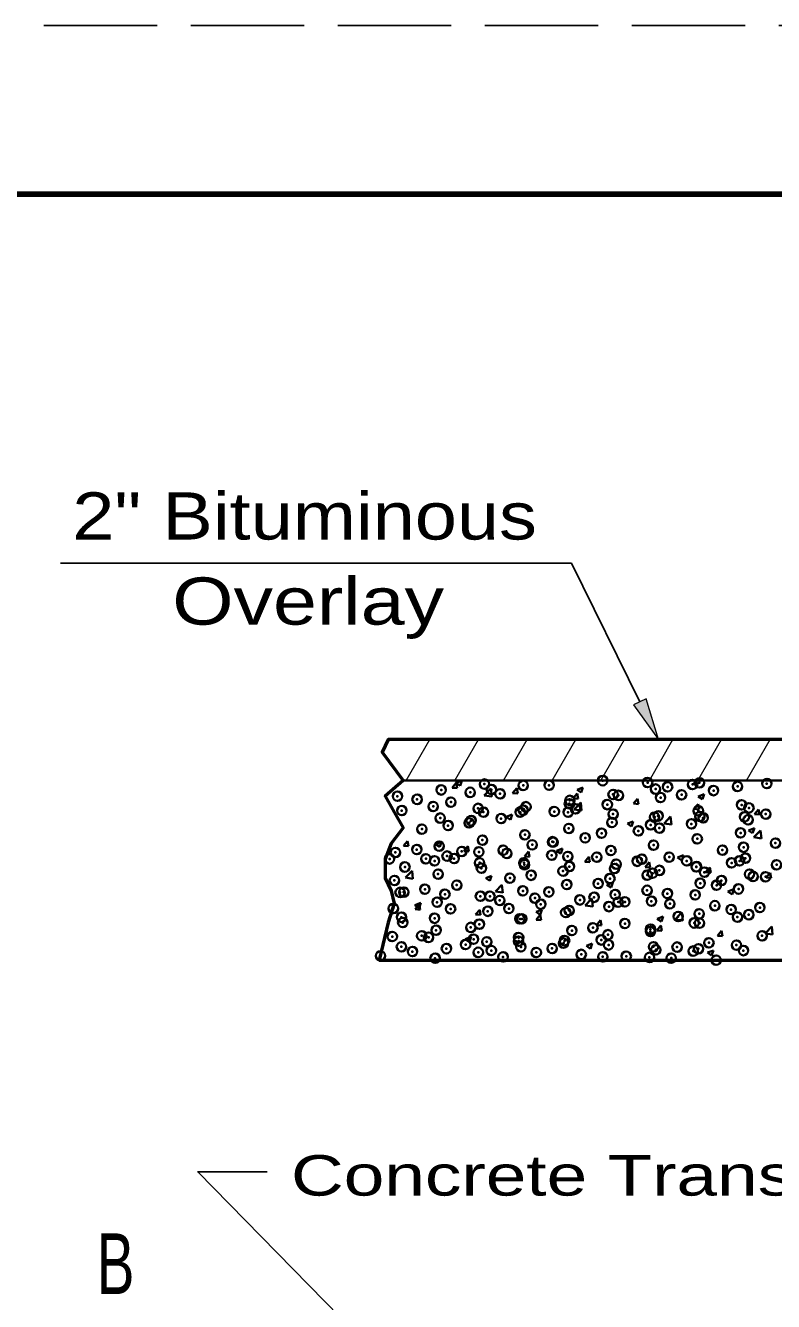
# Model space of a CAD drawing. Extents: x 14 to 49.3, y 28 to 50.
# Drawn here: x 17.83 to 20.049, y 46.258 to 50.044 of the extents above; entities that cross this region are included whole.
import ezdxf

# ---------------------------------------------------------------- set-up
doc = ezdxf.new("R2010")
doc.units = 0
doc.header["$LTSCALE"] = 0.056
doc.header["$PDMODE"] = 32
doc.header["$PDSIZE"] = 0.028
doc.linetypes.add('LONG_DASHED', pattern=[7.5, 6, -1.5])
for name, color, linetype, lineweight in [('1', 7, 'Continuous', 35), ('3', 7, 'Continuous', 13), ('5', 7, 'Continuous', 35)]:
    doc.layers.add(name, color=color, linetype=linetype, lineweight=lineweight)

msp = doc.modelspace()

# ---------------------------------------------------------------- hatches: boundary and pattern name
at = {"layer": '3'}
msp.add_hatch(color=256, dxfattribs=at).paths.add_polyline_path([(19.671, 48.04683), (19.63367, 48.02842), (19.70767, 47.92558), (19.70767, 47.92558)])

# ---------------------------------------------------------------- linework, layer by layer
at = {"layer": '1', "linetype": 'LONG_DASHED', "lineweight": 25}
msp.add_line((49.17658, 50.04392), (13.97658, 50.04392), dxfattribs=at)
at = {"layer": '1', "lineweight": 158}
msp.add_line((49.09325, 49.54392), (16.59325, 49.54392), dxfattribs=at)
at = {"layer": '1', "lineweight": 13}
for p, q in [((18.95892, 47.804), (19.02917, 47.92558)), ((19.10325, 47.804), (19.1735, 47.92558)), ((19.24767, 47.804), (19.31783, 47.92558)), ((19.392, 47.804), (19.46217, 47.92558)), ((19.53633, 47.804), (19.6065, 47.92558)), ((19.68067, 47.804), (19.75083, 47.92558)), ((19.825, 47.804), (19.89517, 47.92558)), ((19.96933, 47.804), (20.0395, 47.92558))]:
    msp.add_line(p, q, dxfattribs=at)
at = {"layer": '1'}
for p, q in [((18.94333, 47.798), (18.94608, 47.79758)), ((18.94608, 47.79758), (18.94575, 47.80017)), ((20.38492, 47.804), (18.95017, 47.804)), ((19.09583, 47.7825), (19.10783, 47.79692)), ((19.09583, 47.7825), (19.11075, 47.78125)), ((19.10692, 47.79667), (19.12442, 47.80342)), ((19.10692, 47.79667), (19.11942, 47.78833)), ((19.11075, 47.78117), (19.10783, 47.79692)), ((19.11942, 47.78833), (19.1245, 47.80342)), ((19.19067, 47.75967), (19.21017, 47.77992)), ((19.21292, 47.75617), (19.21017, 47.77992)), ((19.27508, 47.76683), (19.28717, 47.78117)), ((19.29008, 47.7655), (19.28717, 47.78117)), ((19.46625, 47.77667), (19.48375, 47.78342)), ((19.46625, 47.77667), (19.47867, 47.76825)), ((19.47867, 47.76825), (19.48375, 47.78342)), ((19.19067, 47.75967), (19.21292, 47.75617)), ((19.27508, 47.76683), (19.29008, 47.7655)), ((19.45442, 47.75117), (19.4665, 47.7655)), ((19.45442, 47.75117), (19.46933, 47.74983)), ((19.4575, 47.71825), (19.47692, 47.73858)), ((19.46942, 47.74983), (19.4665, 47.7655)), ((19.47975, 47.71483), (19.47692, 47.73858)), ((19.63375, 47.73542), (19.64583, 47.74983)), ((19.63375, 47.73542), (19.64867, 47.73417)), ((19.64867, 47.73417), (19.64583, 47.74983)), ((19.8255, 47.75667), (19.843, 47.76333)), ((19.8255, 47.75667), (19.83792, 47.74825)), ((19.838, 47.74825), (19.843, 47.76333)), ((19.25617, 47.696), (19.27367, 47.70275)), ((19.26858, 47.68767), (19.27367, 47.70275)), ((19.4575, 47.71825), (19.47967, 47.71483)), ((19.81308, 47.71975), (19.82508, 47.73417)), ((19.81308, 47.71975), (19.828, 47.7185)), ((19.828, 47.71842), (19.82508, 47.73417)), ((19.99233, 47.70408), (20.00442, 47.71842)), ((19.99233, 47.70408), (20.00733, 47.70275)), ((20.00733, 47.70275), (20.00442, 47.71842)), ((19.25617, 47.696), (19.26858, 47.68767)), ((19.61542, 47.676), (19.633, 47.68275)), ((19.61542, 47.676), (19.62792, 47.66758)), ((19.62792, 47.66758), (19.633, 47.68275)), ((19.72425, 47.67692), (19.74375, 47.69717)), ((19.72425, 47.67692), (19.74375, 47.69717)), ((19.72425, 47.67692), (19.7465, 47.67342)), ((19.7465, 47.67342), (19.74375, 47.69717)), ((19.97475, 47.656), (19.99225, 47.66267)), ((19.98717, 47.64758), (19.99225, 47.66267)), ((18.95117, 47.61017), (18.96325, 47.6245)), ((18.96617, 47.60883), (18.96325, 47.6245)), ((19.04608, 47.61542), (19.06358, 47.62208)), ((19.05858, 47.607), (19.06367, 47.62208)), ((19.97475, 47.656), (19.98717, 47.64758)), ((19.99108, 47.6355), (20.01058, 47.65583)), ((19.99108, 47.6355), (20.01333, 47.63208)), ((20.01333, 47.63208), (20.01058, 47.65583)), ((18.95117, 47.61017), (18.96608, 47.60883)), ((19.04608, 47.61542), (19.05858, 47.607)), ((19.1305, 47.5945), (19.1425, 47.60883)), ((19.1305, 47.5945), (19.14542, 47.59317)), ((19.14542, 47.59317), (19.14258, 47.60883)), ((19.30983, 47.57875), (19.32183, 47.59317)), ((19.32475, 47.5775), (19.32183, 47.59317)), ((19.40542, 47.59542), (19.42292, 47.60208)), ((19.40542, 47.59542), (19.41783, 47.587)), ((19.41783, 47.587), (19.42292, 47.60208)), ((19.30983, 47.57875), (19.32475, 47.5775)), ((19.48908, 47.56308), (19.50117, 47.5775)), ((19.48908, 47.56308), (19.50408, 47.56175)), ((19.50408, 47.56175), (19.50117, 47.57742)), ((19.66842, 47.54742), (19.6805, 47.56175)), ((19.66842, 47.54742), (19.68333, 47.54608)), ((19.68342, 47.54608), (19.6805, 47.56175)), ((19.76467, 47.57533), (19.78217, 47.58208)), ((19.76467, 47.57533), (19.77708, 47.567)), ((19.77717, 47.567), (19.78217, 47.58208)), ((19.84775, 47.53175), (19.85983, 47.54608)), ((19.86267, 47.53042), (19.85983, 47.54608)), ((18.957, 47.51608), (18.9765, 47.53642)), ((18.957, 47.51608), (18.97925, 47.51267)), ((18.97925, 47.51267), (18.9765, 47.53642)), ((19.19533, 47.51475), (19.21283, 47.5215)), ((19.19533, 47.51475), (19.20775, 47.50633)), ((19.20783, 47.50633), (19.21283, 47.5215)), ((19.84775, 47.53175), (19.86267, 47.53042)), ((20.02708, 47.516), (20.03908, 47.53042)), ((20.02708, 47.516), (20.042, 47.51475)), ((20.042, 47.51475), (20.03908, 47.53042)), ((19.22383, 47.47475), (19.24325, 47.495)), ((19.22383, 47.47475), (19.246, 47.47133)), ((19.24608, 47.47125), (19.24325, 47.495)), ((19.55467, 47.49475), (19.57217, 47.50142)), ((19.55467, 47.49475), (19.56708, 47.48633)), ((19.56708, 47.48633), (19.57217, 47.50142)), ((19.91392, 47.47467), (19.93142, 47.48142)), ((19.91392, 47.47467), (19.92633, 47.46633)), ((19.92633, 47.46633), (19.93142, 47.48142)), ((18.98525, 47.43408), (19.00283, 47.44083)), ((18.98525, 47.43408), (18.99775, 47.42575)), ((18.98583, 47.42208), (18.99792, 47.4365)), ((18.99775, 47.42575), (19.00283, 47.44083)), ((19.00083, 47.42083), (18.99792, 47.4365)), ((19.49058, 47.43333), (19.51008, 47.45367)), ((19.49058, 47.43333), (19.51283, 47.42992)), ((19.51283, 47.42992), (19.51008, 47.45367)), ((18.98583, 47.42208), (19.00083, 47.42083)), ((19.16517, 47.40642), (19.17725, 47.42075)), ((19.16517, 47.40642), (19.18008, 47.40508)), ((19.18017, 47.40508), (19.17725, 47.42075)), ((19.3445, 47.39075), (19.3565, 47.40508)), ((19.34458, 47.41408), (19.36208, 47.42083)), ((19.34458, 47.41408), (19.357, 47.40567)), ((19.35942, 47.38942), (19.35658, 47.40508)), ((19.357, 47.40567), (19.36208, 47.42083)), ((19.70383, 47.39408), (19.72133, 47.40075)), ((19.71633, 47.38567), (19.72133, 47.40075)), ((19.75742, 47.392), (19.77692, 47.41225)), ((19.77967, 47.3885), (19.77692, 47.41225)), ((19.3445, 47.39075), (19.35942, 47.38942)), ((19.52383, 47.37508), (19.53583, 47.38942)), ((19.52383, 47.37508), (19.53875, 47.37375)), ((19.53875, 47.37375), (19.53583, 47.38942)), ((19.70308, 47.35933), (19.71517, 47.37375)), ((19.70308, 47.35933), (19.71808, 47.35808)), ((19.70383, 47.39408), (19.71625, 47.38567)), ((19.71808, 47.35808), (19.71517, 47.37375)), ((19.75742, 47.392), (19.77967, 47.3885)), ((19.88242, 47.34367), (19.8945, 47.358)), ((19.89742, 47.34233), (19.8945, 47.358)), ((20.02425, 47.35058), (20.04367, 47.37092)), ((20.0465, 47.34717), (20.04375, 47.37092)), ((19.1345, 47.33342), (19.152, 47.34017)), ((19.1345, 47.33342), (19.14692, 47.32508)), ((19.147, 47.32508), (19.152, 47.34017)), ((19.49383, 47.31342), (19.51133, 47.32017)), ((19.50625, 47.30508), (19.51133, 47.32017)), ((19.88242, 47.34367), (19.89733, 47.34233)), ((20.02425, 47.35058), (20.0465, 47.34717)), ((19.49383, 47.31342), (19.50625, 47.30508)), ((19.85308, 47.29342), (19.87058, 47.30017)), ((19.85308, 47.29342), (19.8655, 47.285)), ((19.8655, 47.285), (19.87058, 47.30017))]:
    msp.add_line(p, q, dxfattribs=at)
at = {"layer": '1', "lineweight": 53}
for points in [[(20.38492, 47.92558), (18.90558, 47.92558), (18.88775, 47.88817), (18.95017, 47.804)], [(18.95017, 47.804), (18.89667, 47.75725), (18.92342, 47.7105), (18.95017, 47.66375), (18.9145, 47.617), (18.89667, 47.57025), (18.89667, 47.51417), (18.9145, 47.47675), (18.92342, 47.43933), (18.90558, 47.38325), (18.87883, 47.271)], [(18.87883, 47.271), (23.89617, 47.271), (23.90508, 47.29908), (23.88725, 47.34583), (23.86942, 47.39258), (23.89617, 47.43933), (23.92292, 47.47675), (23.914, 47.51417), (23.87833, 47.57958), (23.8605, 47.63567), (23.89617, 47.66375), (23.914, 47.77592), (23.914, 47.79467)]]:
    msp.add_lwpolyline(points, dxfattribs=at)
at = {"layer": '1'}
for p in [(19.54217, 47.80358), (19.67558, 47.79792), (19.829, 47.79742), (19.06308, 47.776), (19.14933, 47.76892), (19.1915, 47.79358), (19.21192, 47.77717), (19.23758, 47.76483), (19.30658, 47.78967), (19.38342, 47.78992), (19.57292, 47.76267), (19.58908, 47.76), (19.69917, 47.77875), (19.73492, 47.785), (19.7765, 47.76158), (19.80908, 47.79225), (19.87117, 47.774), (19.9425, 47.78667), (20.029, 47.79483), (18.93325, 47.75725), (18.99142, 47.74817), (19.03933, 47.727), (19.09183, 47.73983), (19.17275, 47.72133), (19.31467, 47.72633), (19.44333, 47.735), (19.44458, 47.74508), (19.556, 47.7325), (19.71392, 47.75333), (19.95433, 47.73183), (19.97617, 47.72258), (18.946, 47.71483), (19.06008, 47.69275), (19.15175, 47.68492), (19.18842, 47.71033), (19.24083, 47.691), (19.2975, 47.71), (19.30625, 47.71567), (19.39875, 47.71183), (19.43967, 47.71008), (19.46133, 47.72008), (19.57317, 47.70442), (19.69617, 47.6955), (19.70658, 47.69875), (19.826, 47.71425), (19.83042, 47.69758), (19.84008, 47.69317), (19.96325, 47.69617), (19.9735, 47.6875), (20.02583, 47.70442), (19.00592, 47.65992), (19.08358, 47.67033), (19.14617, 47.67858), (19.4415, 47.66192), (19.53883, 47.6475), (19.56983, 47.6795), (19.64808, 47.65467), (19.68458, 47.6725), (19.71067, 47.66292), (19.80542, 47.67542), (19.95133, 47.64858), (19.057, 47.6095), (19.18542, 47.62717), (19.31167, 47.64317), (19.333, 47.61325), (19.393, 47.6225), (19.39558, 47.62142), (19.49025, 47.63392), (19.69308, 47.61225), (19.82292, 47.631), (20.05475, 47.61833), (18.90992, 47.57125), (18.92717, 47.59075), (18.99067, 47.59925), (19.01783, 47.57175), (19.08042, 47.58), (19.10142, 47.57242), (19.12408, 47.59358), (19.17508, 47.59242), (19.24717, 47.59742), (19.25758, 47.58792), (19.391, 47.58233), (19.4385, 47.57867), (19.5245, 47.57667), (19.56683, 47.59625), (19.65792, 47.571), (19.73958, 47.57683), (19.8975, 47.59758), (19.96008, 47.60583), (19.96583, 47.57342), (18.95558, 47.54742), (19.04333, 47.56567), (19.17683, 47.56), (19.18233, 47.54392), (19.30867, 47.55992), (19.31025, 47.55433), (19.4245, 47.53533), (19.44375, 47.54875), (19.57717, 47.54308), (19.58233, 47.55608), (19.64492, 47.56433), (19.71067, 47.53742), (19.79142, 47.56542), (19.81992, 47.54775), (19.82008, 47.54842), (19.92483, 47.55975), (19.94825, 47.56542), (20.05825, 47.55408), (18.92417, 47.50758), (19.054, 47.52633), (19.26717, 47.51458), (19.32975, 47.52283), (19.43542, 47.49542), (19.5285, 47.49833), (19.56383, 47.513), (19.67425, 47.52333), (19.69008, 47.529), (19.83175, 47.499), (19.84408, 47.53183), (19.89433, 47.50725), (19.97758, 47.52617), (19.989, 47.51967), (20.02575, 47.5185), (18.94092, 47.47217), (18.952, 47.47308), (19.01458, 47.48133), (19.07433, 47.4665), (19.10933, 47.49383), (19.17933, 47.46067), (19.20783, 47.46083), (19.30558, 47.47667), (19.38267, 47.47333), (19.51658, 47.4575), (19.57917, 47.46575), (19.67383, 47.47817), (19.73417, 47.4685), (19.81692, 47.46458), (19.88, 47.4935), (19.94525, 47.48217), (18.92108, 47.42433), (19.05092, 47.44308), (19.09108, 47.42325), (19.23692, 47.44825), (19.264, 47.42425), (19.34125, 47.45525), (19.35867, 47.43675), (19.44258, 47.41842), (19.47475, 47.44958), (19.56075, 47.42983), (19.58833, 47.44342), (19.60817, 47.44392), (19.687, 47.44583), (19.74167, 47.43833), (19.87508, 47.43267), (19.92325, 47.42108), (20.00858, 47.427), (18.94525, 47.39825), (18.94883, 47.38275), (19.0435, 47.39525), (19.20142, 47.416), (19.29675, 47.39342), (19.30258, 47.3935), (19.43242, 47.41217), (19.766, 47.40042), (19.81383, 47.38133), (19.82858, 47.40867), (19.82967, 47.381), (19.94217, 47.39892), (19.97542, 47.406), (19.00517, 47.34333), (19.04792, 47.35983), (19.151, 47.36833), (19.17625, 47.3775), (19.45083, 47.35892), (19.51342, 47.36717), (19.55775, 47.34658), (19.60808, 47.37958), (19.68383, 47.35592), (19.684, 47.36258), (20.01533, 47.34325), (18.91808, 47.34108), (18.94492, 47.31083), (19.02567, 47.33875), (19.07842, 47.30517), (19.13567, 47.31742), (19.15917, 47.33308), (19.19825, 47.32567), (19.29258, 47.3275), (19.29292, 47.33808), (19.2995, 47.31025), (19.39225, 47.30592), (19.42608, 47.32183), (19.42933, 47.329), (19.53808, 47.33092), (19.5595, 47.31617), (19.69292, 47.31058), (19.76275, 47.31), (19.82642, 47.30492), (19.8575, 47.3225), (19.93917, 47.31575), (18.88308, 47.28417), (18.97775, 47.29658), (19.04483, 47.27667), (19.17325, 47.29425), (19.21183, 47.2995), (19.2465, 47.28083), (19.34533, 47.29392), (19.47875, 47.28825), (19.54233, 47.281), (19.61225, 47.28258), (19.68092, 47.27933), (19.70017, 47.30175), (19.74567, 47.277), (19.81083, 47.29808), (19.87908, 47.27133), (19.95983, 47.29925)]:
    msp.add_point(p, dxfattribs=at)
at = {"layer": '3', "lineweight": 25}
for points in [[(19.65233, 48.03767), (19.44925, 48.44917), (17.93383, 48.44917)], [(19.09325, 45.87442), (18.34083, 46.643), (18.54708, 46.643)]]:
    msp.add_lwpolyline(points, dxfattribs=at)
at = {"layer": '3'}
msp.add_lwpolyline([(19.671, 48.04683), (19.63367, 48.02842), (19.70767, 47.92558), (19.70767, 47.92558)], close=True, dxfattribs=at)

# ---------------------------------------------------------------- texts
for s, height, width, p in [('2" Bituminous', 0.14, 1.2, (17.96858, 48.51892)), ('Overlay', 0.14, 1.25, (18.26517, 48.26642)), ('Concrete Transition Pavement with 2" Bituminous Overlay', 0.12, 1.35, (18.61742, 46.5725))]:
    msp.add_text(s, height=height, dxfattribs=dict(at, width=width)).set_placement(p)
at = {"layer": '5', "width": 0.7}
msp.add_text('B', height=0.18, dxfattribs=at).set_placement((18.04083, 46.28058))

doc.saveas('drawing.dxf')
